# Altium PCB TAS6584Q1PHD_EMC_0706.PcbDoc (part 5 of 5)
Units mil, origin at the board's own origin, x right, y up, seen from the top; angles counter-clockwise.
Board outline 7086.61 x 5118.11 mil, 6 copper layers (Top Layer, GND02, SIG03, SIG04, GND05, Bottom Layer), stack 60.484 mil thick; 461 components, 247 nets, 1337 pads, 1658 vias.
Unrouted connection lines stored in the file: 67.
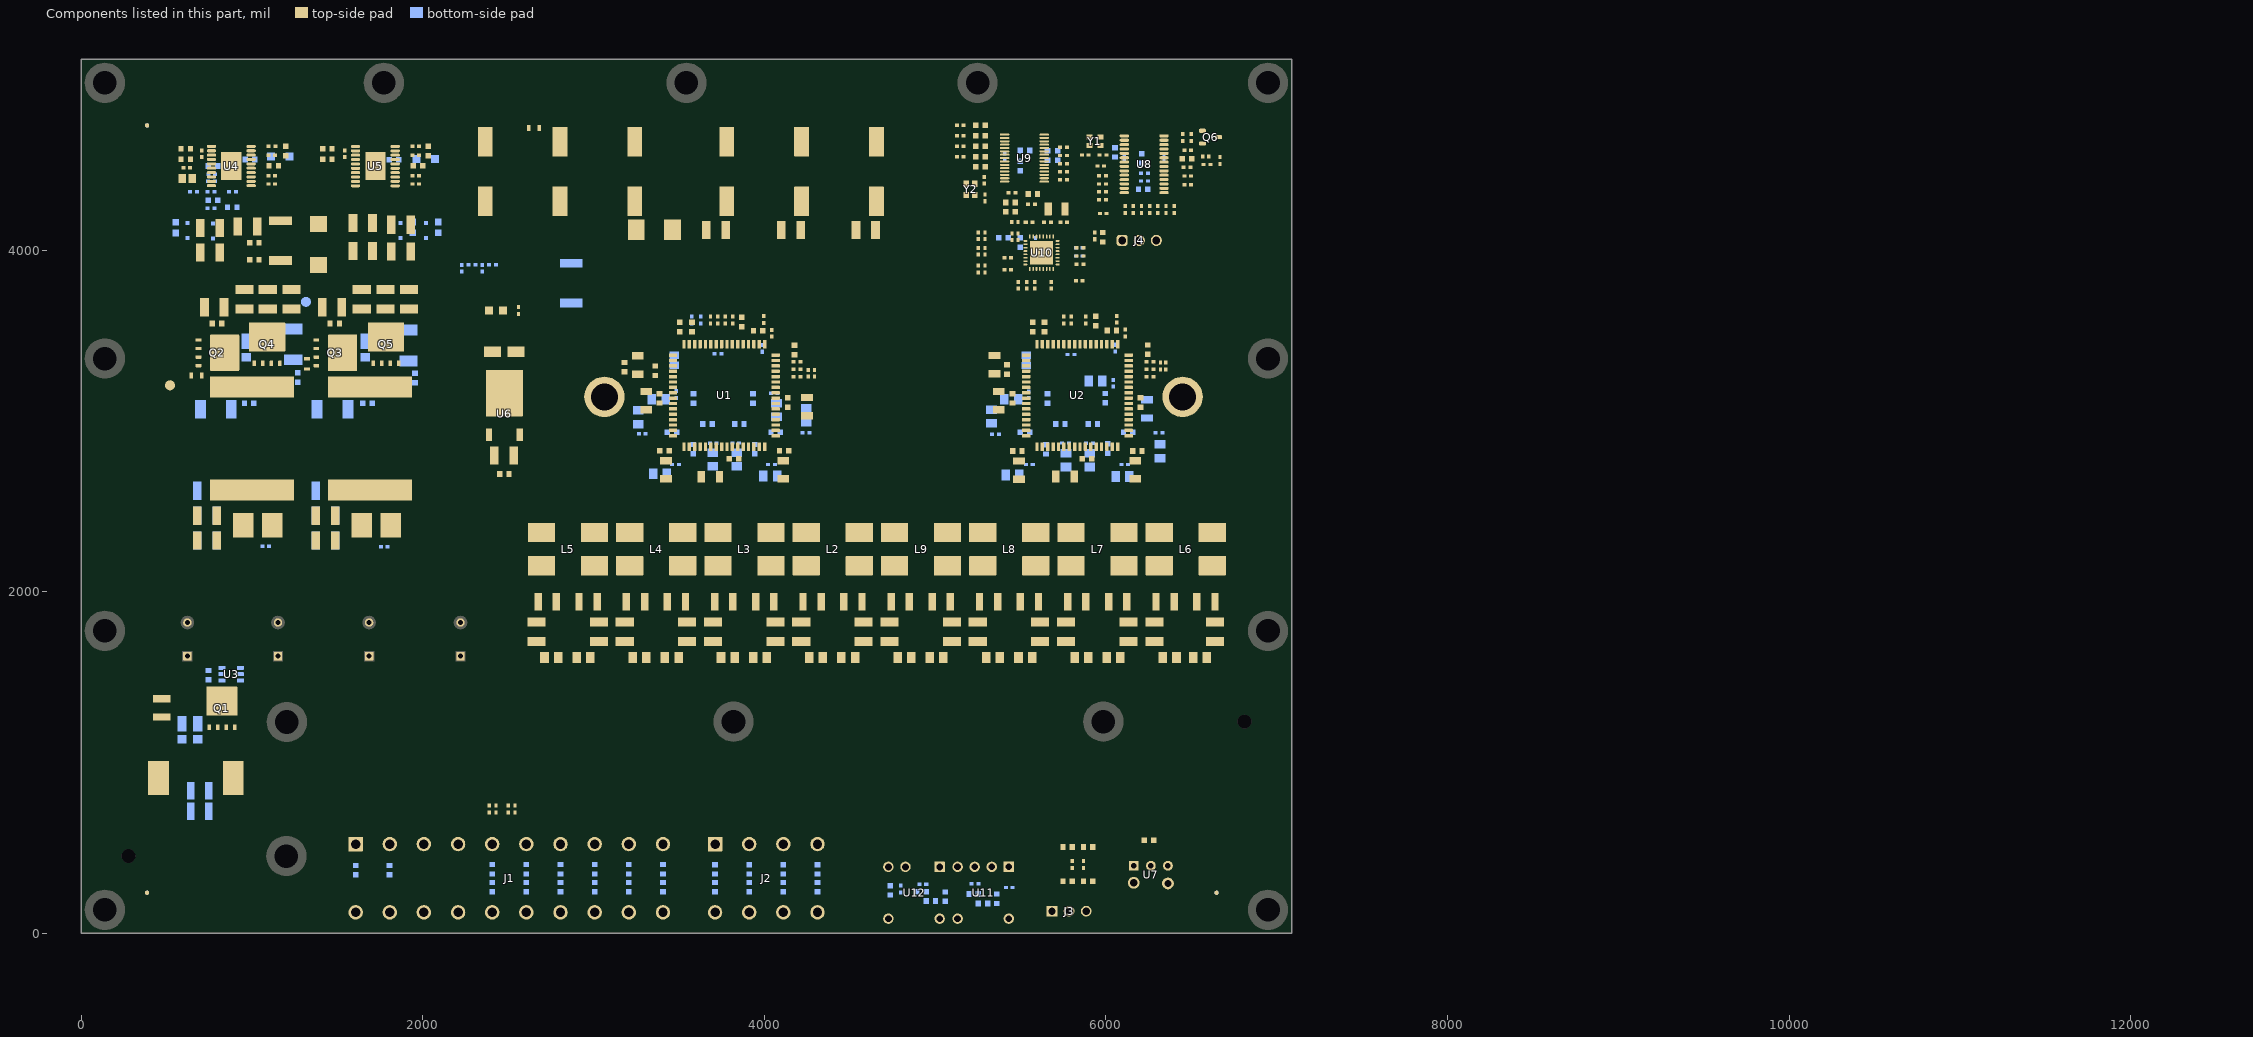
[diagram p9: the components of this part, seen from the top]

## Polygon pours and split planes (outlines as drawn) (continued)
PVDD on Bottom Layer "PVDD_L06_P512" (solid, pour order 512): 6161.37,3175.73 6161.37,3160.16 6209.66,3111.86 6274,3111.86 6274,3144.86 6282.71,3153.58 6282.71,3177.81 6273.4,3187.12 6169.44,3187.12 6169.42,3187.1
14_4V on Bottom Layer "14_4V_L06_P458" (solid, pour order 458): 1462.35,2644.8 1509.6,2644.8 1574.66,2579.74 1574.66,2459.68 1757.57,2276.77 1757.57,2185.43 1456.44,2185.43 1456.22,2640
14_4V on Bottom Layer "14_4V_L06_P455" (solid, pour order 455): 767.93,2644.8 815.17,2644.8 880.23,2579.74 880.23,2459.68 1063.14,2276.77 1063.14,2185.43 762.01,2185.43 761.79,2640
GND on GND02 (split plane): 7066.52,20.1 20.1,20.1 20.1,5098.01 7066.52,5098.01
V_boost on GND02 (split plane): 3372.9,3953.29 1949.99,3953.29 1852.48,4050.8 1850.83,4051.91 1848.87,4052.29 1009.53,4052.29 1009.53,4273.32 1965.78,4273.32 1967.73,4273.71 1969.38,4274.82 2186.47,4491.9 3372.9,4491.9
GND on GND05 (split plane): 7066.52,20.1 20.1,20.1 20.1,5098.01 7066.52,5098.01

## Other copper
Top Layer:
  region net VCC: 2347.19,3594.41 2347.19,3516.98 2430.59,3516.67 2430.59,3594.41
  region net 14_4V: 2221,2717.74 2221,2640.31 2304.4,2640 2304.4,2717.74
  region net SPK_OUT8+: 6645.24,1734.04 6701.31,1734.04 6701.31,1540.87 6684.08,1523.64 6616.66,1523.64 6570.43,1569.88 6570.43,1659.23
  region net NetC94_1: 6383.6,2211 6237.02,2211 6231.02,2205 6231.02,1837.12 6239.18,1828.96 6320.6,1828.96 6335.76,1844.12 6335.76,2048.73 6391.02,2104 6391.02,2203.58
  region net SPK_OUT8-: 6285.4,1734.55 6230.67,1734.55 6230.67,1538.75 6245.33,1524.09 6304.54,1524.09 6355.14,1574.69 6355.14,1664.8
  region net NetC93_1: 6548.73,2211 6695.31,2211 6701.62,2204.69 6701.62,1826.97 6607.49,1826.97 6595.72,1838.75 6595.71,2049.59 6541.31,2104 6541.31,2203.58
  region net GND: 6540.12,1988.9 6387.93,1988.9 6383.02,1984 6383.02,1573 6392.02,1564 6537.02,1564 6545.51,1572.48 6545.5,1983.52
  region net SPK_OUT7+: 6128.38,1734.04 6184.45,1734.04 6184.45,1540.87 6167.22,1523.64 6099.8,1523.64 6053.57,1569.88 6053.57,1659.23
  region net NetC96_1: 5866.74,2211 5720.16,2211 5714.16,2205 5714.16,1837.12 5722.32,1828.96 5803.74,1828.96 5818.9,1844.12 5818.9,2048.73 5874.16,2104 5874.16,2203.58
  region net SPK_OUT7-: 5768.54,1734.55 5713.81,1734.55 5713.81,1538.75 5728.47,1524.09 5787.68,1524.09 5838.28,1574.69 5838.28,1664.8
  region net NetC95_1: 6031.87,2211 6178.45,2211 6184.76,2204.69 6184.76,1826.97 6090.63,1826.97 6078.85,1838.75 6078.85,2049.59 6024.45,2104 6024.45,2203.58
  region net GND: 6023.26,1988.9 5871.07,1988.9 5866.16,1984 5866.16,1573 5875.16,1564 6020.16,1564 6028.65,1572.48 6028.64,1983.52
  region net SPK_OUT6+: 5611.52,1734.04 5667.59,1734.04 5667.59,1540.87 5650.36,1523.64 5582.94,1523.64 5536.71,1569.88 5536.71,1659.23
  region net NetC98_1: 5349.88,2211 5203.3,2211 5197.3,2205 5197.3,1837.12 5205.46,1828.96 5286.88,1828.96 5302.04,1844.12 5302.04,2048.73 5357.3,2104 5357.3,2203.58
  region net SPK_OUT6-: 5251.68,1734.55 5196.95,1734.55 5196.95,1538.75 5211.61,1524.09 5270.81,1524.09 5321.42,1574.69 5321.42,1664.8
  region net NetC97_1: 5515.01,2211 5661.59,2211 5667.9,2204.69 5667.9,1826.97 5573.77,1826.97 5561.99,1838.75 5561.99,2049.59 5507.59,2104 5507.59,2203.58
  region net GND: 5506.4,1988.9 5354.21,1988.9 5349.3,1984 5349.3,1573 5358.3,1564 5503.3,1564 5511.78,1572.48 5511.78,1983.52
  region net SPK_OUT5+: 5094.66,1734.04 5150.73,1734.04 5150.73,1540.87 5133.5,1523.64 5066.08,1523.64 5019.85,1569.88 5019.85,1659.23
  region net NetC100_1: 4833.02,2211 4686.44,2211 4680.44,2205 4680.44,1837.12 4688.6,1828.96 4770.02,1828.96 4785.18,1844.12 4785.18,2048.73 4840.44,2104 4840.44,2203.58
  region net SPK_OUT5-: 4734.82,1734.55 4680.09,1734.55 4680.09,1538.75 4694.75,1524.09 4753.95,1524.09 4804.56,1574.69 4804.56,1664.8
  region net NetC99_1: 4998.15,2211 5144.73,2211 5151.04,2204.69 5151.04,1826.97 5056.91,1826.97 5045.13,1838.75 5045.13,2049.59 4990.73,2104 4990.73,2203.58
  region net GND: 4989.54,1988.9 4837.35,1988.9 4832.44,1984 4832.44,1573 4841.44,1564 4986.44,1564 4994.92,1572.48 4994.92,1983.52
  region net SPK_OUT4+: 4577.8,1734.04 4633.86,1734.04 4633.87,1540.87 4616.64,1523.64 4549.22,1523.64 4502.99,1569.88 4502.99,1659.23
  region net NetC36_1: 4316.16,2211 4169.58,2211 4163.58,2205 4163.58,1837.12 4171.74,1828.96 4253.16,1828.96 4268.32,1844.12 4268.32,2048.73 4323.58,2104 4323.58,2203.58
  region net SPK_OUT4-: 4217.96,1734.55 4163.23,1734.55 4163.23,1538.75 4177.89,1524.09 4237.09,1524.09 4287.7,1574.69 4287.69,1664.8
  region net NetC35_1: 4481.29,2211 4627.87,2211 4634.18,2204.69 4634.18,1826.97 4540.05,1826.97 4528.27,1838.75 4528.27,2049.59 4473.87,2104 4473.87,2203.58
  region net GND: 4472.68,1988.9 4320.49,1988.9 4315.58,1984 4315.58,1573 4324.58,1564 4469.58,1564 4478.06,1572.48 4478.06,1983.52
  region net SPK_OUT3+: 4060.94,1734.04 4117,1734.04 4117.01,1540.87 4099.78,1523.64 4032.36,1523.64 3986.13,1569.88 3986.13,1659.23
  region net NetC38_1: 3799.3,2211 3652.72,2211 3646.72,2205 3646.72,1837.12 3654.88,1828.96 3736.3,1828.96 3751.46,1844.12 3751.46,2048.73 3806.72,2104 3806.72,2203.58
  region net SPK_OUT3-: 3701.1,1734.55 3646.37,1734.55 3646.37,1538.75 3661.03,1524.09 3720.23,1524.09 3770.84,1574.69 3770.83,1664.8
  region net NetC37_1: 3964.43,2211 4111,2211 4117.32,2204.69 4117.32,1826.97 4023.19,1826.97 4011.41,1838.75 4011.41,2049.59 3957,2104 3957,2203.58
  region net GND: 3955.82,1988.9 3803.63,1988.9 3798.72,1984 3798.72,1573 3807.72,1564 3952.72,1564 3961.2,1572.48 3961.2,1983.52
  region net SPK_OUT2+: 3544.08,1734.04 3600.14,1734.04 3600.14,1540.87 3582.91,1523.64 3515.5,1523.64 3469.27,1569.88 3469.27,1659.23
  region net NetC40_1: 3282.44,2211 3135.86,2211 3129.86,2205 3129.86,1837.12 3138.02,1828.96 3219.44,1828.96 3234.6,1844.12 3234.6,2048.73 3289.86,2104 3289.86,2203.58
  region net SPK_OUT2-: 3184.24,1734.55 3129.51,1734.55 3129.51,1538.75 3144.17,1524.09 3203.37,1524.09 3253.98,1574.69 3253.97,1664.8
  region net NetC39_1: 3447.57,2211 3594.14,2211 3600.46,2204.69 3600.46,1826.97 3506.33,1826.97 3494.55,1838.75 3494.55,2049.59 3440.14,2104 3440.14,2203.58
  region net GND: 3438.96,1988.9 3286.77,1988.9 3281.86,1984 3281.86,1573 3290.86,1564 3435.86,1564 3444.34,1572.48 3444.34,1983.52
  region net GND: 2922.1,1988.9 2769.9,1988.9 2765,1984 2765,1573 2774,1564 2919,1564 2927.48,1572.48 2927.48,1983.52
  region net NetC41_1: 2930.71,2211 3077.28,2211 3083.59,2204.69 3083.6,1826.97 2989.47,1826.97 2977.69,1838.75 2977.69,2049.59 2923.28,2104 2923.28,2203.58
  region net SPK_OUT1-: 2667.38,1734.55 2612.65,1734.55 2612.65,1538.75 2627.31,1524.09 2686.51,1524.09 2737.11,1574.69 2737.11,1664.8
  region net PVDD: 5493.36,3237 5366.35,3237 5338.14,3208.78 5338.14,3182.62 5375.76,3145 5483.36,3145 5493.28,3154.93
  region net PVDD: 6162.08,2746.46 6136.37,2746.46 6058.73,2824.1 6058.73,2874.41 6107.95,2923.62 6157.16,2923.62 6157.16,2899.02 6171.92,2884.25 6171.92,2756.3
  region net PVDD: 5850.46,2638.8 5783.3,2638.79 5783.3,2712 5793.99,2722.69 5793.99,2802.34 5816.4,2824.74 5853.62,2824.74 5876.65,2801.71 5876.65,2756.36 5876.65,2664.99
  region net PVDD: 5534.42,2745.69 5503.29,2745.69 5493.45,2755.54 5493.45,2883.49 5508.21,2898.25 5508.21,2919.39 5556.88,2919.39 5606.64,2869.63 5606.64,2817.91
  region net PVDD: 3467.06,2745.69 3435.94,2745.69 3426.09,2755.54 3426.09,2883.49 3440.86,2898.25 3440.86,2919.39 3489.52,2919.39 3539.28,2869.63 3539.28,2817.91
  region net PVDD: 3783.1,2638.8 3715.94,2638.79 3715.94,2712 3731.99,2728.05 3731.99,2807.69 3749.04,2824.74 3786.26,2824.74 3809.29,2801.71 3809.29,2756.36 3809.29,2664.99
  region net PVDD: 4094.72,2746.46 4069.02,2746.46 3991.38,2824.1 3991.38,2874.41 4040.59,2923.62 4089.8,2923.62 4089.8,2899.02 4104.57,2884.25 4104.57,2756.3
  pour cut-out: 5209.88,4757.63 5209.88,4522.46 5312.48,4522.46 5312.48,4757.63
  region net GND: 520,1426.96 509.1,1437.86 374.5,1437.86 370,1433.36 370,1330 380,1320 399.42,1320 410,1330.58 410,1345 415,1350 515,1350 520,1355
  region net NetC19_1: 4480,2288.15 4632,2288.15 4642,2298.15 4642,2509.15 4629,2522.15 4479,2522.15 4470,2513.15 4470,2298.15
  region net NetC20_1: 4169.37,2288.15 4321.37,2288.15 4331.37,2298.15 4331.37,2509.15 4318.37,2522.15 4168.37,2522.15 4159.37,2513.15 4159.37,2298.15
  region net NetC21_1: 3963.16,2288.15 4115.16,2288.15 4125.16,2298.15 4125.16,2509.15 4112.16,2522.15 3962.16,2522.15 3953.16,2513.15 3953.16,2298.15
  region net NetC22_1: 3652.53,2288.15 3804.53,2288.15 3814.53,2298.15 3814.53,2509.15 3801.53,2522.15 3651.53,2522.15 3642.53,2513.15 3642.53,2298.15
  region net NetC23_1: 3446.32,2288.15 3598.32,2288.15 3608.32,2298.15 3608.32,2509.15 3595.32,2522.15 3445.32,2522.15 3436.32,2513.15 3436.32,2298.15
  region net NetC24_1: 3135.69,2288.15 3287.69,2288.15 3297.69,2298.15 3297.69,2509.15 3284.69,2522.15 3134.69,2522.15 3125.69,2513.15 3125.69,2298.15
  region net NetC25_1: 2929.48,2288.15 3081.48,2288.15 3091.48,2298.15 3091.48,2509.15 3078.48,2522.15 2928.48,2522.15 2919.48,2513.15 2919.48,2298.15
  region net NetC26_1: 2618.85,2288.15 2770.85,2288.15 2780.85,2298.15 2780.85,2509.15 2767.85,2522.15 2617.85,2522.15 2608.85,2513.15 2608.85,2298.15
  region net PVDD: 3426.01,3237 3299,3237 3274.3,3212.3 3274.3,3179.1 3308.4,3145 3416,3145 3425.93,3154.93
  region net GND: 7061.12,25.49 6811.02,25.49 6811.02,1178.52 6817.09,1178.52 6829,1180.89 6840.22,1185.54 6850.31,1192.28 6858.9,1200.87 6865.64,1210.96 6870.29,1222.18 6872.66,1234.09 6872.66,1240.16 6872.66,1246.23 6870.29,1258.14 6865.64,1269.35 6858.9,1279.45 6850.31,1288.03 6840.22,1294.78 6829,1299.42 6817.09,1301.79 6811.02,1301.79 6811.02,4842.52 275.59,4842.52 275.59,514.39 269.52,514.39 257.61,512.02 246.39,507.38 236.3,500.63 227.71,492.05 220.97,481.95 216.32,470.73 213.95,458.83 213.95,452.76 213.95,446.69 216.32,434.78 220.97,423.56 227.71,413.47 236.3,404.88 246.39,398.14 257.61,393.49 269.52,391.12 275.59,391.12 275.59,25.49 25.49,25.49 25.49,5092.62 7061.12,5092.62
  region net GND: 6811.02,1301.79 6804.95,1301.79 6793.04,1299.42 6781.83,1294.78 6771.73,1288.03 6763.15,1279.45 6756.4,1269.35 6751.76,1258.14 6749.39,1246.23 6749.39,1240.16 6749.39,1234.09 6751.76,1222.18 6756.4,1210.96 6763.15,1200.87 6771.73,1192.28 6781.83,1185.54 6793.04,1180.89 6804.95,1178.52 6811.02,1178.52 6811.02,1102.36 1377.95,1102.36 1377.95,314.96 275.59,314.96 275.59,391.12 281.66,391.12 293.57,393.49 304.79,398.14 314.88,404.88 323.47,413.47 330.21,423.56 334.86,434.78 337.23,446.69 337.23,452.76 337.23,458.83 334.86,470.73 330.21,481.95 323.47,492.05 314.88,500.63 304.79,507.38 293.57,512.02 281.66,514.39 275.59,514.39 275.59,590.55 1062.99,590.55 1062.99,1377.95 6811.02,1377.95
  pour cut-out: 2801.24,2542.54 2801.24,2052.36 2588.89,2052.36 2588.89,2542.54
  pour cut-out: 2895.04,2542.54 2895.04,2052.36 3107.39,2052.36 3107.39,2542.54
  pour cut-out: 3411.88,2542.54 3411.88,2052.36 3624.23,2052.36 3624.23,2542.54
  pour cut-out: 3318.08,2542.54 3318.08,2052.36 3105.73,2052.36 3105.73,2542.54
  pour cut-out: 3928.72,2542.54 3928.72,2052.36 4141.07,2052.36 4141.07,2542.54
  pour cut-out: 3834.92,2542.54 3834.92,2052.36 3622.57,2052.36 3622.57,2542.54
  pour cut-out: 4445.56,2542.54 4445.56,2052.36 4657.91,2052.36 4657.91,2542.54
  pour cut-out: 4351.76,2542.54 4351.76,2052.36 4139.41,2052.36 4139.41,2542.54
  pour cut-out: 4962.4,2542.54 4962.4,2052.36 5174.75,2052.36 5174.75,2542.54
  pour cut-out: 4868.6,2542.54 4868.6,2052.36 4656.25,2052.36 4656.25,2542.54
  pour cut-out: 5479.24,2542.54 5479.24,2052.36 5691.59,2052.36 5691.59,2542.54
  pour cut-out: 5385.44,2542.54 5385.44,2052.36 5173.09,2052.36 5173.09,2542.54
  pour cut-out: 5996.07,2542.54 5996.07,2052.36 6208.43,2052.36 6208.43,2542.54
  pour cut-out: 5902.28,2542.54 5902.28,2052.36 5689.93,2052.36 5689.93,2542.54
  pour cut-out: 6512.91,2542.54 6512.91,2052.36 6725.27,2052.36 6725.27,2542.54
  pour cut-out: 6419.12,2542.54 6419.12,2052.36 6206.76,2052.36 6206.76,2542.54
  region net NetC42_1: 2765.58,2211 2619,2211 2613,2205 2613,1837.12 2621.16,1828.96 2702.58,1828.96 2717.74,1844.12 2717.74,2048.73 2773,2104 2773,2203.58
  region net SPK_OUT1+: 3027.22,1734.04 3083.28,1734.04 3083.28,1540.87 3066.05,1523.64 2998.64,1523.64 2952.41,1569.88 2952.41,1659.23
  region net NetC84_1: 4686.21,2288.15 4838.21,2288.15 4848.21,2298.15 4848.21,2509.15 4835.21,2522.15 4685.21,2522.15 4676.21,2513.15 4676.21,2298.15
  region net NetC83_1: 4996.84,2288.15 5148.84,2288.15 5158.84,2298.15 5158.84,2509.15 5145.84,2522.15 4995.84,2522.15 4986.84,2513.15 4986.84,2298.15
  region net NetC82_1: 5203.05,2288.15 5355.05,2288.15 5365.05,2298.15 5365.05,2509.15 5352.05,2522.15 5202.05,2522.15 5193.05,2513.15 5193.05,2298.15
  region net NetC81_1: 5513.68,2288.15 5665.68,2288.15 5675.68,2298.15 5675.68,2509.15 5662.68,2522.15 5512.68,2522.15 5503.68,2513.15 5503.68,2298.15
  region net NetC80_1: 5719.89,2288.15 5871.89,2288.15 5881.89,2298.15 5881.89,2509.15 5868.89,2522.15 5718.89,2522.15 5709.89,2513.15 5709.89,2298.15
  region net NetC79_1: 6030.52,2288.15 6182.52,2288.15 6192.52,2298.15 6192.52,2509.15 6179.52,2522.15 6029.52,2522.15 6020.52,2513.15 6020.52,2298.15
  region net NetC78_1: 6236.73,2288.15 6388.73,2288.15 6398.73,2298.15 6398.73,2509.15 6385.73,2522.15 6235.73,2522.15 6226.73,2513.15 6226.73,2298.15
  region net NetC77_1: 6547.36,2288.15 6700.8,2288.15 6700.8,2517.71 6696.36,2522.15 6546.36,2522.15 6537.36,2513.15 6537.36,2298.15
  region net BAT_IN: 825.62,1012.4 962.96,1012.4 962.96,668.76 947.7,653.5 795.13,653.5 774.22,674.4 774.22,961.01
  region net NetC126_1: 516.84,812.4 392.6,812.4 360,845 360,1265 385,1290 619.93,1290 674.93,1235 860.17,1235 865.17,1230 865.17,1140.17 742.8,1017.79 575.24,1017.8 522.69,965.24 522.69,818.25
  text "'.Layer_Name'" at 6726,-216 h80
SIG04:
  pour cut-out: 1200.93,291.92 ccw(c1200.93,451.92) 1360.93,451.92 ccw(c1200.93,451.92) 1200.93,611.92 ccw(c1200.93,451.92) 1040.93,451.92 ccw(c1200.93,451.92)
  pour cut-out: 6449.14,2981.16 ccw(c6449.14,3141.16) 6609.14,3141.16 ccw(c6449.14,3141.16) 6449.14,3301.16 ccw(c6449.14,3141.16) 6289.14,3141.16 ccw(c6449.14,3141.16)
  pour cut-out: 3063.14,2981.16 ccw(c3063.14,3141.16) 3223.14,3141.16 ccw(c3063.14,3141.16) 3063.14,3301.16 ccw(c3063.14,3141.16) 2903.14,3141.16 ccw(c3063.14,3141.16)
  region net SPK_OUT8-: 4258.79,471.61 4258.79,538.25 4292.32,571.78 4570.59,571.78 4835.83,837.02 5828.95,837.02 6217,1225.07 6217,1666.13 6312.23,1666.18 6338.43,1639.98 6338.43,1255.44 5843.6,760.61 4865.98,760.61 4576.98,471.61
  region net SPK_OUT4-: 3359.01,474.25 3359.01,735.2 3682.88,1059.06 3891.94,1059.06 4162.11,1329.23 4162.11,1665.25 4225.51,1665.49 4276.65,1614.35 4276.65,1327.36 3913.46,964.17 3774.63,964.17 3450.79,640.33 3450.79,474.2
  region net SPK_OUT4+: 3359.17,77 3354.24,81.93 3354.24,153.76 3371.8,171.32 3450.79,171.32 3468.17,188.7 3468.17,617.98 3791.08,940.89 3905.71,940.89 4538.54,1573.72 4538.54,1623.25 4581.47,1666.18 4631,1666.18 4631,1547.12 4596.88,1513 4573.84,1513 3917.9,857.07 3535.17,474.34 3535.17,166.23 3445.95,77
  region net SPK_OUT5-: 3659,473 3752.09,473 3762.11,483.03 3762.11,601.33 4031.56,870.77 4149.86,870.77 4785,1505.91 4785,1674.75 4668.15,1674.75 4668.15,1547.79 4596.64,1476.28 4552.98,1476.28 3659.1,582.4
  region net SPK_OUT5+: 3664,77 3659.07,81.93 3659.07,153.76 3676.63,171.32 3755.61,171.32 3773,188.7 3773,588.93 4041.14,857.07 4156.44,857.07 4812.38,1513 5015,1513 5047,1545 5047,1610 5103.18,1666.18 5149,1666.18 5149,1499 5056.8,1406.8 4877.23,1406.8 4279.33,808.9 4081.29,808.9 3840,567.62 3840,166.23 3750.77,77
  region net SPK_OUT6-: 3859,473 3952.09,473 3962.11,483.03 3962.11,590.63 4116.66,745.17 4355.19,745.17 4878.42,1268.4 5188.16,1268.4 5314.6,1394.83 5314.6,1674.75 5185,1674.75 5185,1495.98 5064.02,1375 4871.22,1375 4294.91,798.68 4086.37,798.68 3859.09,571.4
  region net SPK_OUT6+: 3864,77 3859.07,81.93 3859.07,153.76 3876.63,171.32 3955.61,171.32 3973,188.7 3973,577 4130.07,734.07 4362.42,734.08 4820.59,1192.25 5141.32,1192.25 5551.03,1601.96 5551.03,1640.77 5576.44,1666.18 5670,1666.18 5670,1529.06 5201.46,1060.52 4788.47,1060.52 4423.86,695.91 4181.55,695.91 4040,554.36 4040,166.23 3950.77,77
  region net SPK_OUT7-: 4059,473 4152.09,473 4162.11,483.03 4162.11,546.17 4262.74,646.8 4492.02,646.8 4798.62,953.39 5286.13,953.39 5815.46,1482.73 5815.46,1674.75 5712.82,1674.75 5712.82,1541.18 5211.64,1040 4785.23,1040 4431.08,685.85 4200.27,685.85 4059.06,544.64
  region net SPK_OUT7+: 4064,77 4059.07,81.93 4059.07,153.76 4076.63,171.32 4155.61,171.32 4173,188.7 4173,542.67 4264.05,633.73 4495.45,633.73 4802.61,940.89 5297.89,940.89 5850,1493 5987,1493 6083.35,1589.35 6083.36,1645.36 6104.18,1666.18 6180,1666.18 6180,1528 6073,1421 5915.45,1421 5354.19,856.2 4833.35,856.2 4561.25,584.1 4285.45,584.1 4240,538.65 4240,166.23 4150.77,77
  region net SPK_OUT3-: 3647.85,1665 3647.85,1561.39 3161,1074.54 3161,463 3232.89,463 3252.91,483.03 3252.92,1060.61 3751.46,1559.15 3751.46,1665
  region net SPK_OUT3+: 3163,77 3244,77 3341.28,174.28 3341.28,1012.55 3775.71,1446.99 4039.51,1446.99 4116.22,1523.7 4116.22,1666 4054.97,1666 4006,1617.03 4006,1555.78 3981.22,1531 3752.96,1531 3274.03,1052.07 3274.03,192.44 3252.92,171.32 3179.63,171.32 3161,152.68 3161,77
  region net SPK_OUT2-: 3129,1665 3105.56,1641.56 3105.56,1449.56 2961,1305 2961,463 3032.89,463 3052.91,483.03 3052.92,1256.3 3238,1441.38 3238,1665
  region net SPK_OUT2+: 2963,77 2953,87 2953,143.65 2980.67,171.32 3051.32,171.32 3069.07,189.07 3069.07,1178.03 3556.6,1665.57 3574.04,1665.57 3599,1640.6 3599,1543.11 3138.5,1082.61 3138.5,152.68 3062.82,77
  region net SPK_OUT1+: 2763,77 2753,87 2753,143.65 2780.67,171.32 2851.32,171.32 2869.07,189.07 2869.07,1394.07 2961.97,1486.97 2961.97,1595.19 3032.35,1665.57 3073.67,1665.57 3083.28,1655.95 3083.28,1464.28 2938.5,1319.5 2938.5,157.12 2858.38,77
  region net SPK_OUT1-: 2612.86,1665.57 2612.86,1427.22 2760.83,1279.25 2760.83,463 2853,463 2853,1355.2 2727.16,1481.04 2727.16,1616.25 2677.93,1665.48
  text "'.Layer_Name'" at 6726,-216 h80
SIG03:
  pour cut-out: 1200.93,291.92 ccw(c1200.93,451.92) 1360.93,451.92 ccw(c1200.93,451.92) 1200.93,611.92 ccw(c1200.93,451.92) 1040.93,451.92 ccw(c1200.93,451.92)
  pour cut-out: 3063.14,2981.16 ccw(c3063.14,3141.16) 3223.14,3141.16 ccw(c3063.14,3141.16) 3063.14,3301.16 ccw(c3063.14,3141.16) 2903.14,3141.16 ccw(c3063.14,3141.16)
  region net 14_4V: 2221,2717.74 2221,2640.31 2304.4,2640 2304.4,2717.74
  region net SPK_OUT4-: 3359.01,474.25 3359.01,735.2 3682.88,1059.06 3891.94,1059.06 4162.11,1329.23 4162.11,1665.25 4225.51,1665.49 4276.65,1614.35 4276.65,1327.36 3913.46,964.17 3774.63,964.17 3450.79,640.33 3450.79,474.2
  region net SPK_OUT4+: 3359.17,77 3354.24,81.93 3354.24,153.76 3371.8,171.32 3450.79,171.32 3468.17,188.7 3468.17,617.98 3791.08,940.89 3905.71,940.89 4538.54,1573.72 4538.54,1623.25 4581.47,1666.18 4631,1666.18 4631,1547.12 4596.88,1513 4573.84,1513 3917.9,857.07 3535.17,474.34 3535.17,166.23 3445.95,77
  region net SPK_OUT5-: 3659,473 3752.09,473 3762.11,483.03 3762.11,601.33 4031.56,870.77 4149.86,870.77 4785,1505.91 4785,1674.75 4668.15,1674.75 4668.15,1547.79 4596.64,1476.28 4552.98,1476.28 3659.1,582.4
  region net SPK_OUT5+: 3664,77 3659.07,81.93 3659.07,153.76 3676.63,171.32 3755.61,171.32 3773,188.7 3773,588.93 4041.14,857.07 4156.44,857.07 4812.38,1513 5015,1513 5047,1545 5047,1610 5103.18,1666.18 5149,1666.18 5149,1499 5056.8,1406.8 4877.23,1406.8 4279.33,808.9 4081.29,808.9 3840,567.62 3840,166.23 3750.77,77
  region net SPK_OUT6-: 3859,473 3952.09,473 3962.11,483.03 3962.11,590.63 4116.66,745.17 4355.19,745.17 4878.42,1268.4 5188.16,1268.4 5314.6,1394.83 5314.6,1674.75 5185,1674.75 5185,1495.98 5064.02,1375 4871.22,1375 4294.91,798.68 4086.37,798.68 3859.09,571.4
  region net SPK_OUT6+: 3864,77 3859.07,81.93 3859.07,153.76 3876.63,171.32 3955.61,171.32 3973,188.7 3973,577 4130.07,734.07 4362.42,734.08 4820.59,1192.25 5141.32,1192.25 5551.03,1601.96 5551.03,1640.77 5576.44,1666.18 5670,1666.18 5670,1529.06 5201.46,1060.52 4788.47,1060.52 4423.86,695.91 4181.55,695.91 4040,554.36 4040,166.23 3950.77,77
  region net SPK_OUT7-: 4059,473 4152.09,473 4162.11,483.03 4162.11,546.17 4262.74,646.8 4492.02,646.8 4798.62,953.39 5286.13,953.39 5815.46,1482.73 5815.46,1674.75 5712.82,1674.75 5712.82,1541.18 5211.64,1040 4785.23,1040 4431.08,685.85 4200.27,685.85 4059.06,544.64
  region net SPK_OUT7+: 4064,77 4059.07,81.93 4059.07,153.76 4076.63,171.32 4155.61,171.32 4173,188.7 4173,542.67 4264.05,633.73 4495.45,633.73 4802.61,940.89 5297.89,940.89 5850,1493 5987,1493 6083.35,1589.35 6083.36,1645.36 6104.18,1666.18 6180,1666.18 6180,1528 6073,1421 5915.45,1421 5354.19,856.2 4833.35,856.2 4561.25,584.1 4285.45,584.1 4240,538.65 4240,166.23 4150.77,77
  region net SPK_OUT8+: 4266,77 4258.79,84.21 4258.79,153.63 4279.44,174.28 4384.73,174.28 4417.48,207.03 4417.48,291.07 4871.58,745.17 5843.97,745.17 6579,1480.2 6579,1588 6658,1667 6694,1667 6694,1504.16 5852.78,662.94 4896.77,662.94 4493.14,259.31 4493.14,161.36 4408.78,77 4310.83,77
  region net SPK_OUT8-: 4258.79,471.61 4258.79,538.25 4292.32,571.78 4570.59,571.78 4835.83,837.02 5828.95,837.02 6217,1225.07 6217,1666.13 6312.23,1666.18 6338.43,1639.98 6338.43,1255.44 5843.6,760.61 4865.98,760.61 4576.98,471.61
  region net SPK_OUT3-: 3647.85,1665 3647.85,1561.39 3161,1074.54 3161,463 3232.89,463 3252.91,483.03 3252.92,1060.61 3751.46,1559.15 3751.46,1665
  region net SPK_OUT3+: 3163,77 3244,77 3341.28,174.28 3341.28,1012.55 3775.71,1446.99 4039.51,1446.99 4116.22,1523.7 4116.22,1666 4054.97,1666 4006,1617.03 4006,1555.78 3981.22,1531 3752.96,1531 3274.03,1052.07 3274.03,192.44 3252.92,171.32 3179.63,171.32 3161,152.68 3161,77
  region net SPK_OUT2-: 3129,1665 3105.56,1641.56 3105.56,1449.56 2961,1305 2961,463 3032.89,463 3052.91,483.03 3052.92,1256.3 3238,1441.38 3238,1665
  region net SPK_OUT2+: 2963,77 2953,87 2953,143.65 2980.67,171.32 3051.32,171.32 3069.07,189.07 3069.07,1178.03 3556.6,1665.57 3574.04,1665.57 3599,1640.6 3599,1543.11 3138.5,1082.61 3138.5,152.68 3062.82,77
  region net SPK_OUT1+: 2763,77 2753,87 2753,143.65 2780.67,171.32 2851.32,171.32 2869.07,189.07 2869.07,1394.07 2961.97,1486.97 2961.97,1595.19 3032.35,1665.57 3073.67,1665.57 3083.28,1655.95 3083.28,1464.28 2938.5,1319.5 2938.5,157.12 2858.38,77
  region net SPK_OUT1-: 2612.86,1665.57 2612.86,1427.22 2760.83,1279.25 2760.83,463 2853,463 2853,1355.2 2727.16,1481.04 2727.16,1616.25 2677.93,1665.48
  text "'.Layer_Name'" at 6726,-216 h80
Bottom Layer:
  pour cut-out: 3063.14,2981.16 ccw(c3063.14,3141.16) 3223.14,3141.16 ccw(c3063.14,3141.16) 3063.14,3301.16 ccw(c3063.14,3141.16) 2903.14,3141.16 ccw(c3063.14,3141.16)
  pour cut-out: 6449,2982 ccw(c6449,3142) 6609,3142 ccw(c6449,3142) 6449,3302 ccw(c6449,3142) 6289,3142 ccw(c6449,3142)
  region net SW2: 1448.45,3490.03 1448.45,3294.73 1609.29,3294.45 1609.53,3490.37
  region net SW1: 753,3486.96 753,3291.66 913.84,3291.38 914.08,3487.29
  region net GND: 652.98,887.8 662.8,877.98 662.8,664.09 652.8,654.09 506.77,654.09 500.92,659.94 500.92,875.14 513.58,887.8
  region net VCC: 2347.19,3594.41 2347.19,3516.98 2430.59,3516.67 2430.59,3594.41
  region net GND: 4363.83,358.2 4363.83,291.74 4347.11,275.02 4274.84,275.02 4257.83,292.04 4257.83,357.9 4270.59,370.67 4351.36,370.67
  region net GND: 4164,357.85 4164,291.38 4147.28,274.67 4075.02,274.67 4058,291.69 4058,357.55 4070.77,370.32 4151.54,370.32
  region net GND: 3963.83,358.2 3963.83,291.74 3947.11,275.02 3874.84,275.02 3857.83,292.04 3857.83,357.9 3870.59,370.67 3951.36,370.67
  region net GND: 3763.83,358.2 3763.83,291.74 3747.11,275.02 3674.84,275.02 3657.83,292.04 3657.83,357.9 3670.59,370.67 3751.36,370.67
  region net GND: 3459,358.2 3459,291.74 3442.28,275.02 3370.02,275.02 3353,292.04 3353,357.9 3365.77,370.67 3446.54,370.67
  region net GND: 3259,358.2 3259,291.74 3242.28,275.02 3170.02,275.02 3153,292.04 3153,357.9 3165.77,370.67 3246.54,370.67
  region net GND: 3059,358.2 3059,291.74 3042.28,275.02 2970.02,275.02 2953,292.04 2953,357.9 2965.77,370.67 3046.54,370.67
  region net GND: 2859,358.2 2859,291.74 2842.28,275.02 2770.02,275.02 2753,292.04 2753,357.9 2765.77,370.67 2846.54,370.67
  region net GND: 2659,358.2 2659,291.74 2642.28,275.02 2570.02,275.02 2553,292.04 2553,357.9 2565.77,370.67 2646.54,370.67
  region net GND: 2459,358.2 2459,291.74 2442.28,275.02 2370.02,275.02 2353,292.04 2353,357.9 2365.77,370.67 2446.54,370.67
  region net BAT_IN: 733.44,655.46 723.44,665.46 723.44,893.32 754.44,924.32 961.27,924.32 965.05,920.54 965.05,667.46 953.06,655.46
  region net NetC126_1: 711.55,1160.96 724.65,1147.87 724.65,1028.2 714.24,1017.8 512.59,1017.8 501.93,1028.46 501.93,1152.6 510.3,1160.96
  region net 14_4V: 525,1180 515,1190 515,1417.86 546,1448.86 701.14,1448.86 720.62,1429.38 720.62,1186.38 714.24,1180
  region net SPK_OUT1+: 2859.01,85.01 2859,247 2850,256 2762,256 2753,247 2753,87 2763,77 2851,77
  region net SPK_OUT1-: 2859.01,560.99 2859,399 2850,390 2762,390 2753,399 2753,559 2763,569 2851,569
  region net SPK_OUT2-: 3059.01,560.99 3059,399 3050,390 2962,390 2953,399 2953,559 2963,569 3051,569
  region net SPK_OUT2+: 3059.01,85.01 3059,247 3050,256 2962,256 2953,247 2953,87 2963,77 3051,77
  region net SPK_OUT3-: 3259.01,560.99 3259,399 3250,390 3162,390 3153,399 3153,559 3163,569 3251,569
  region net SPK_OUT3+: 3259.01,85.01 3259,247 3250,256 3162,256 3153,247 3153,87 3163,77 3251,77
  region net SPK_OUT4-: 3459.01,560.99 3459,399 3450,390 3362,390 3353,399 3353,559 3363,569 3451,569
  region net SPK_OUT4+: 3459.01,85.01 3459,247 3450,256 3362,256 3353,247 3353,87 3363,77 3451,77
  region net SPK_OUT5-: 3764.01,560.64 3764,398.64 3755,389.65 3667,389.65 3658,398.65 3658,558.64 3668,568.64 3756,568.65
  region net SPK_OUT5+: 3764.01,84.65 3764,246.65 3755,255.65 3667,255.65 3658,246.65 3658,86.65 3668,76.65 3756,76.64
  region net SPK_OUT6-: 3964.01,560.64 3964,398.64 3955,389.65 3867,389.65 3858,398.65 3858,558.64 3868,568.64 3956,568.65
  region net SPK_OUT6+: 3964.01,84.65 3964,246.65 3955,255.65 3867,255.65 3858,246.65 3858,86.65 3868,76.65 3956,76.64
  region net SPK_OUT7-: 4164.01,560.64 4164,398.64 4155,389.65 4067,389.65 4058,398.65 4058,558.64 4068,568.64 4156,568.65
  region net SPK_OUT7+: 4164.01,84.65 4164,246.65 4155,255.65 4067,255.65 4058,246.65 4058,86.65 4068,76.65 4156,76.64
  region net SPK_OUT8-: 4364.01,560.64 4364,398.64 4355,389.65 4267,389.65 4258,398.65 4258,558.64 4268,568.64 4356,568.65
  region net SPK_OUT8+: 4364.01,84.65 4364,246.65 4355,255.65 4267,255.65 4258,246.65 4258,86.65 4268,76.65 4356,76.64
  region net Audio_IN1-: 2459.01,560.99 2459,399 2450,390 2362,390 2353,399 2353,559 2363,569 2451,569
  region net Audio_IN2-: 2659.01,560.99 2659,399 2650,390 2562,390 2553,399 2553,559 2563,569 2651,569
  region net Audio_IN1+: 2352.99,85.01 2353,247 2362,256 2450,256 2459,247 2459,87 2449,77 2361,77
  region net Audio_IN2+: 2552.99,85.01 2553,247 2562,256 2650,256 2659,247 2659,87 2649,77 2561,77
  text "'.Layer_Name'" at 6726,-216 h80
GND02 (plane layer: these items are gaps in the copper):
  lines w10: 1004.43,4047.2 1848.87,4047.2 1947.88,3948.19 3378,3948.19 3378,4497 2184.36,4497 1965.78,4278.42 1004.43,4278.42 1004.43,4047.2
  text "'.Layer_Name'" at 6726,-216 h80
GND05 (plane layer: these items are gaps in the copper):
  text "'.Layer_Name'" at 6726,-216 h80
Multi-Layer:
  pour cut-out: 275.59,391.12 cw(c275.59,452.76) 213.95,452.76 cw(c275.59,452.76) 275.59,514.39 cw(c275.59,452.76) 337.23,452.76 cw(c275.59,452.76)
  pour cut-out: 6811.02,1178.52 cw(c6811.02,1240.16) 6749.39,1240.16 cw(c6811.02,1240.16) 6811.02,1301.79 cw(c6811.02,1240.16) 6872.66,1240.16 cw(c6811.02,1240.16)

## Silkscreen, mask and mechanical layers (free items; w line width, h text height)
Top Overlay:
  drawing of 425 lines, arcs and shapes, not listed
  text "Layer" at 8000.09,4970 h60
  text "Name" at 8410,4970 h60
  text "Material" at 9339.74,4970 h60
  text "Thickness" at 10199.51,4970 h60
  text "Constant" at 10849.35,4970 h60
  text "Board Layer Stack" at 11419.21,4970 h60
  text "Top Overlay" at 8410,4850 h60
  text "Top Solder" at 8410,4730 h60
  text "Solder Resist" at 9339.74,4730 h60
  text "0.50mil" at 10199.51,4730 h60
  text "3.3" at 10849.35,4730 h60
  text "1" at 8000.09,4610 h60
  text "Top Layer" at 8410,4610 h60
  text "1.42mil" at 10199.51,4610 h60
  text "Dielectric 1" at 8410,4490 h60
  text "FR-4" at 9339.74,4490 h60
  text "6.00mil" at 10199.51,4490 h60
  text "4.2" at 10849.35,4490 h60
  text "2" at 8000.09,4370 h60
  text "GND02" at 8410,4370 h60
  text "1.42mil" at 10199.51,4370 h60
  text "Dielectric 2" at 8410,4250 h60
  text "FR-4" at 9339.74,4250 h60
  text "10.00mil" at 10199.51,4250 h60
  text "4.2" at 10849.35,4250 h60
  text "3" at 8000.09,4130 h60
  text "SIG03" at 8410,4130 h60
  text "1.40mil" at 10199.51,4130 h60
  text "Dielectric 3" at 8410,4010 h60
  text "FR-4" at 9339.74,4010 h60
  text "20.00mil" at 10199.51,4010 h60
  text "4.2" at 10849.35,4010 h60
  text "4" at 8000.09,3890 h60
  text "SIG04" at 8410,3890 h60
  text "1.42mil" at 10199.51,3890 h60
  text "TAS6584Q1 EMC REF" at 2243.79,3784 h100
  text "Dielectric 4" at 8410,3770 h60
  text "FR-4" at 9339.74,3770 h60
  text "10.00mil" at 10199.51,3770 h60
  text "4.2" at 10849.35,3770 h60
  text "5" at 8000.09,3650 h60
  text "GND05" at 8410,3650 h60
  text "1.42mil" at 10199.51,3650 h60
  text "Dielectric 5" at 8410,3530 h60
  text "FR-4" at 9339.74,3530 h60
  text "6.00mil" at 10199.51,3530 h60
  text "4.2" at 10849.35,3530 h60
  text "6" at 8000.09,3410 h60
  text "Bottom Layer" at 8410,3410 h60
  text "1.42mil" at 10199.51,3410 h60
  text "Bottom Solder" at 8410,3290 h60
  text "Solder Resist" at 9339.74,3290 h60
  text "0.50mil" at 10199.51,3290 h60
  text "3.3" at 10849.35,3290 h60
  text "Bottom Overlay" at 8410,3170 h60
Bottom Overlay:
  circle w10: c5984.25,1240.16 r177.17
  circle w10: c3818.9,1240 r177.17
  circle w10: c1200.79,452.76 r177.17
  circle w10: c1203.18,1237.77 r177.17
  lines w10: 492.13,1.5 492.13,4625.98 6594.49,4625.98 6594.49,1.5
Top Solder:
  region: 275.59,590.55 1062.99,590.55 1062.99,1377.95 6811.02,1377.95 6811.02,1102.36 1377.95,1102.36 1377.95,314.96 275.59,314.96
  region: 275.59,0 275.59,4842.52 6811.02,4842.52 6811.02,0 7086.61,0 7086.61,5118.11 0,5118.11 0,0
Bottom Solder:
  region: 275.59,0 0,0 0,5118.11 7086.61,5118.11 7086.61,0 6811.02,0 6811.02,4842.52 275.59,4842.52
M1 Board Outline:
  the board outline again, w10
DXF:
  pour cut-out: 5984.25,1181.1 cw(c5984.25,1240.16) 5925.2,1240.16 cw(c5984.25,1240.16) 5984.25,1299.21 cw(c5984.25,1240.16) 6043.31,1240.16 cw(c5984.25,1240.16)
  pour cut-out: 3818.9,1181.1 cw(c3818.9,1240.16) 3759.84,1240.16 cw(c3818.9,1240.16) 3818.9,1299.21 cw(c3818.9,1240.16) 3877.95,1240.16 cw(c3818.9,1240.16)
  pour cut-out: 137.8,1712.6 cw(c137.8,1771.65) 78.74,1771.65 cw(c137.8,1771.65) 137.8,1830.71 cw(c137.8,1771.65) 196.85,1771.65 cw(c137.8,1771.65)
  pour cut-out: 137.8,78.74 cw(c137.8,137.8) 78.74,137.8 cw(c137.8,137.8) 137.8,196.85 cw(c137.8,137.8) 196.85,137.8 cw(c137.8,137.8)
  pour cut-out: 6948.82,78.74 cw(c6948.82,137.8) 6889.76,137.8 cw(c6948.82,137.8) 6948.82,196.85 cw(c6948.82,137.8) 7007.87,137.8 cw(c6948.82,137.8)
  pour cut-out: 6948.82,1711.91 cw(c6948.82,1770.97) 6889.76,1770.97 cw(c6948.82,1770.97) 6948.82,1830.02 cw(c6948.82,1770.97) 7007.87,1770.97 cw(c6948.82,1770.97)
  pour cut-out: 6948.82,3307.09 cw(c6948.82,3366.14) 6889.76,3366.14 cw(c6948.82,3366.14) 6948.82,3425.2 cw(c6948.82,3366.14) 7007.87,3366.14 cw(c6948.82,3366.14)
  pour cut-out: 5248.03,4921.26 cw(c5248.03,4980.31) 5188.98,4980.31 cw(c5248.03,4980.32) 5248.03,5039.37 cw(c5248.03,4980.32) 5307.09,4980.31 cw(c5248.03,4980.31)
  pour cut-out: 3543.31,4921.26 cw(c3543.31,4980.31) 3484.25,4980.31 cw(c3543.31,4980.32) 3543.31,5039.37 cw(c3543.31,4980.32) 3602.36,4980.31 cw(c3543.31,4980.31)
  pour cut-out: 1771.65,4921.26 cw(c1771.65,4980.31) 1712.6,4980.31 cw(c1771.65,4980.32) 1771.65,5039.37 cw(c1771.65,4980.32) 1830.71,4980.31 cw(c1771.65,4980.31)
  pour cut-out: 137.8,4921.26 cw(c137.8,4980.31) 78.74,4980.31 cw(c137.8,4980.32) 137.8,5039.37 cw(c137.8,4980.32) 196.85,4980.31 cw(c137.8,4980.31)
  pour cut-out: 137.8,3307.09 cw(c137.8,3366.14) 78.74,3366.14 cw(c137.8,3366.14) 137.8,3425.2 cw(c137.8,3366.14) 196.85,3366.14 cw(c137.8,3366.14)
  pour cut-out: 6948.82,4921.26 cw(c6948.82,4980.31) 6889.76,4980.31 cw(c6948.82,4980.32) 6948.82,5039.37 cw(c6948.82,4980.32) 7007.87,4980.31 cw(c6948.82,4980.31)
  pour cut-out: 1200.79,393.7 cw(c1200.79,452.76) 1141.73,452.76 cw(c1200.79,452.76) 1200.79,511.81 cw(c1200.79,452.76) 1259.84,452.76 cw(c1200.79,452.76)
  pour cut-out: 1203.18,1178.71 cw(c1203.18,1237.77) 1144.12,1237.77 cw(c1203.18,1237.77) 1203.18,1296.82 cw(c1203.18,1237.77) 1262.23,1237.77 cw(c1203.18,1237.77)
  pour cut-out: 275.59,413.39 cw(c275.59,452.76) 236.22,452.76 cw(c275.59,452.76) 275.59,492.13 cw(c275.59,452.76) 314.96,452.76 cw(c275.59,452.76)
  pour cut-out: 6811.02,1200.79 cw(c6811.02,1240.16) 6771.65,1240.16 cw(c6811.02,1240.16) 6811.02,1279.53 cw(c6811.02,1240.16) 6850.39,1240.16 cw(c6811.02,1240.16)
Drill Drawing:
  drawing of 45033 lines, arcs and shapes, not listed
  text "8" at -1867.32,17229.08 h156
  text "8" at -1867.32,17229.08 h156
  text "8" at -1867.32,17229.08 h156
  text "8" at -1867.32,17229.08 h156
  text "8" at -1867.32,17229.08 h156
  text "8" at -1867.32,17229.08 h156
  text "7" at 2257.68,17229.08 h156
  text "7" at 2257.68,17229.08 h156
  text "7" at 2257.68,17229.08 h156
  text "7" at 2257.68,17229.08 h156
  text "7" at 2257.68,17229.08 h156
  text "7" at 2257.68,17229.08 h156
  text "6" at 6382.68,17229.08 h156
  text "6" at 6382.68,17229.08 h156
  text "6" at 6382.68,17229.08 h156
  text "6" at 6382.68,17229.08 h156
  text "6" at 6382.68,17229.08 h156
  text "6" at 6382.68,17229.08 h156
  text "5" at 10507.68,17229.08 h156
  text "5" at 10507.68,17229.08 h156
  text "5" at 10507.68,17229.08 h156
  text "5" at 10507.68,17229.08 h156
  text "5" at 10507.68,17229.08 h156
  text "5" at 10507.68,17229.08 h156
  text "4" at 14632.68,17229.08 h156
  text "4" at 14632.68,17229.08 h156
  text "4" at 14632.68,17229.08 h156
  text "4" at 14632.68,17229.08 h156
  text "4" at 14632.68,17229.08 h156
  text "4" at 14632.68,17229.08 h156
  text "3" at 18757.68,17229.08 h156
  text "3" at 18757.68,17229.08 h156
  text "3" at 18757.68,17229.08 h156
  text "3" at 18757.68,17229.08 h156
  text "3" at 18757.68,17229.08 h156
  text "3" at 18757.68,17229.08 h156
  text "2" at 22882.68,17229.08 h156
  text "2" at 22882.68,17229.08 h156
  text "2" at 22882.68,17229.08 h156
  text "2" at 22882.68,17229.08 h156
  text "2" at 22882.68,17229.08 h156
  text "2" at 22882.68,17229.08 h156
  text "1" at 27007.68,17229.08 h156
  text "1" at 27007.68,17229.08 h156
  text "1" at 27007.68,17229.08 h156
  text "1" at 27007.68,17229.08 h156
  text "1" at 27007.68,17229.08 h156
  text "1" at 27007.68,17229.08 h156
  text "D" at -4082.32,14429.08 h156
  text "D" at -4082.32,14429.08 h156
  text "D" at -4082.32,14429.08 h156
  text "D" at -4082.32,14429.08 h156
  text "D" at -4082.32,14429.08 h156
  text "D" at -4082.32,14429.08 h156
  text "D" at 29230.08,14429.08 h125
  text "D" at 29230.08,14429.08 h125
  text "D" at 29230.08,14429.08 h125
  text "D" at 29230.08,14429.08 h125
  text "D" at 29230.08,14429.08 h125
  text "D" at 29230.08,14429.08 h125
  text "Fab Drawing Notes" at 14617.3,14020.88 h80
  text "BOARD NAME:TAS6584Q1PHD_EMC" at 11517.3,13570.88 h80
  text "BOARD LAYER:  8" at 15317.3,13570.88 h80
  text "BOARD SIZE:  180X 130MM" at 11517.3,13370.88 h80
  text "BOARD THICKNESS: 1.6 MM(+/-10%)" at 15317.3,13370.88 h80
  text "SOLDER MASK: IPC SM-840" at 11517.3,13170.88 h80
  text "SILKSCREEN LAYER: TOP && BOTTOM" at 15317.3,13170.88 h80
  text "CONTROL IMPEDANCE: NO" at 11517.3,12970.88 h80
  text "IMPEDANCE REPORT: NO" at 15317.3,12970.88 h80
  text "SOLDER COLORS:    GREEN            RED                YELLOW               BLACK         OTHER" at 11517.3,12770.88 h80
  text "SILKSCREEN COLORS:WHITE             RED                YELLOW               BLACK         OTHER" at 11517.3,12570.88 h80
  text "SURFACE FINISHED:         HASL(Sn/Pb)                  HASL(Pb-Free)                      IMMERSION GOLD" at 11517.3,12370.88 h80
  text "ENIG                           OSP                                OTHER" at 13560.39,12159.09 h80
  text "BOARD MATERIAL:                FR-4                    FR-4 TG150                           FR-4 TU872" at 11517.3,11970.88 h80
  text "ROGERS 4003                 ROGERS 4350B                              OTHER" at 13007.39,11772.09 h80
  text "VIA TECHNIC:           ALL VIA FILLED                    BY GERBER                                OTHER" at 11517.3,11570.88 h80
  text "INSPECTION STANDARD:          IPC-II           IPC-III         GJB              GB-4588              OTHER" at 11517.3,11370.88 h80
  text "BOW & TWIST TOLERANCE: <=0.75%    HOLES(TOL):+/-0.0762mm   PRESS FIT HOLES(TOL):+/-0.05mm" at 11517.3,11170.88 h80
  text "OPEN WINDOWS: NO                  SPELL MODE:1:1" at 11517.3,10970.88 h80
  text "DATE: 2019-11-12" at 11517.3,10770.88 h80
  text "DESIGNER: zhaojy" at 14237.3,10770.88 h80
  text "DESIGNER: zhaojy@kingbrother.com" at 16237.3,10770.88 h80
  text "OTHER:" at 11517.3,10570.88 h80
  text "V-cut Detail:" at 14817.3,10570.88 h80
  text "T" at 15667.3,10260.88 h80
  text "1/3T" at 16967.3,10260.88 h80
  text "Angle<45" at 16817.3,10070.88 h80
  text "C" at -4082.32,9179.08 h156
  text "C" at -4082.32,9179.08 h156
  text "C" at -4082.32,9179.08 h156
  text "C" at -4082.32,9179.08 h156
  text "C" at -4082.32,9179.08 h156
  text "C" at -4082.32,9179.08 h156
  text "C" at 29230.08,9179.08 h125
  text "C" at 29230.08,9179.08 h125
  text "C" at 29230.08,9179.08 h125
  text "C" at 29230.08,9179.08 h125
  text "C" at 29230.08,9179.08 h125
  text "C" at 29230.08,9179.08 h125
  text "B" at -4082.32,3929.08 h156
  text "B" at -4082.32,3929.08 h156
  text "B" at -4082.32,3929.08 h156
  text "B" at -4082.32,3929.08 h156
  text "B" at -4082.32,3929.08 h156
  text "B" at -4082.32,3929.08 h156
  text "B" at 29230.08,3929.08 h125
  text "B" at 29230.08,3929.08 h125
  text "B" at 29230.08,3929.08 h125
  text "B" at 29230.08,3929.08 h125
  text "B" at 29230.08,3929.08 h125
  text "B" at 29230.08,3929.08 h125
  text "A" at -4082.32,-1320.92 h156
  text "A" at -4082.32,-1320.92 h156
  text "A" at 29230.08,-1320.92 h125
  text "A" at 29230.08,-1320.92 h125
  text "A" at 29230.08,-1320.92 h125
  text "A" at 29230.08,-1320.92 h125
  text "A" at 29230.08,-1320.92 h125
  text "A" at 29230.08,-1320.92 h125
  text "SIZE:A1" at 22180.08,-2735.92 h60
  text "SIZE:A1" at 22180.08,-2735.92 h60
  text "Part No:" at 23663.28,-2810.92 h60
  text "Part No:" at 23663.28,-2810.92 h60
  text "Revision:" at 24788.28,-2810.92 h60
  text "Revision:" at 24788.28,-2810.92 h60
  text "Data:" at 25888.28,-2810.92 h60
  text "Data:" at 25888.28,-2810.92 h60
  text "Designer:" at 26838.28,-2810.92 h60
  text "Designer:" at 26838.28,-2810.92 h60
  text "QA:" at 27988.28,-2810.92 h60
  text "QA:" at 27988.28,-2810.92 h60
  text "DIMENSIONS:INCHES" at 22180.08,-2935.92 h60
  text "DIMENSIONS:INCHES" at 22180.08,-2935.92 h60
  text "bomz" at 28062.2,-2999.8 h60
  text "zhaojy" at 26889.9,-3000.06 h60
  text "D2020010023" at 23680.08,-3010.92 h60
  text "1.0" at 25063.28,-3010.92 h60
  text "2020-02-05" at 25888.28,-3010.92 h60
  text "SHEET 1 OF 1" at 22180.08,-3135.92 h60
  text "SHEET 1 OF 1" at 22180.08,-3135.92 h60
  text "8" at -1867.32,-4125.92 h156
  text "8" at -1867.32,-4125.92 h156
  text "8" at -1867.32,-4125.92 h156
  text "8" at -1867.32,-4125.92 h156
  text "8" at -1867.32,-4125.92 h156
  text "8" at -1867.32,-4125.92 h156
  text "7" at 2257.68,-4125.92 h156
  text "7" at 2257.68,-4125.92 h156
  text "7" at 2257.68,-4125.92 h156
  text "7" at 2257.68,-4125.92 h156
  text "7" at 2257.68,-4125.92 h156
  text "7" at 2257.68,-4125.92 h156
  text "6" at 6382.68,-4125.92 h156
  text "6" at 6382.68,-4125.92 h156
  text "6" at 6382.68,-4125.92 h156
  text "6" at 6382.68,-4125.92 h156
  text "6" at 6382.68,-4125.92 h156
  text "6" at 6382.68,-4125.92 h156
  text "5" at 10507.68,-4125.92 h156
  text "5" at 10507.68,-4125.92 h156
  text "5" at 10507.68,-4125.92 h156
  text "5" at 10507.68,-4125.92 h156
  text "5" at 10507.68,-4125.92 h156
  text "5" at 10507.68,-4125.92 h156
  text "4" at 14632.68,-4125.92 h156
  text "4" at 14632.68,-4125.92 h156
  text "4" at 14632.68,-4125.92 h156
  text "4" at 14632.68,-4125.92 h156
  text "4" at 14632.68,-4125.92 h156
  text "4" at 14632.68,-4125.92 h156
  text "3" at 18757.68,-4125.92 h156
  text "3" at 18757.68,-4125.92 h156
  text "3" at 18757.68,-4125.92 h156
  text "3" at 18757.68,-4125.92 h156
  text "3" at 18757.68,-4125.92 h156
  text "3" at 18757.68,-4125.92 h156
  text "2" at 22882.68,-4125.92 h156
  text "2" at 22882.68,-4125.92 h156
  text "2" at 22882.68,-4125.92 h156
  text "2" at 22882.68,-4125.92 h156
  text "2" at 22882.68,-4125.92 h156
  text "2" at 22882.68,-4125.92 h156
  text "1" at 27007.68,-4125.92 h156
  text "1" at 27007.68,-4125.92 h156
  text "1" at 27007.68,-4125.92 h156
  text "1" at 27007.68,-4125.92 h156
  text "1" at 27007.68,-4125.92 h156
  text "1" at 27007.68,-4125.92 h156

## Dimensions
0,-19.69 to 7086.61,-19.69 on M2 Board Dimensions
-19.69,0 to -19.69,5118.11 on M2 Board Dimensions
0,5118.11 to 7086.61,5118.11 on M2 Board Dimensions
7086.61,5118.11 to 7086.61,0 on M2 Board Dimensions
